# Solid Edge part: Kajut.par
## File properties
Author: Administrator
Template: Normal.par
Last saved by: Administrator
Revision: 10
Application: Solid Edge
Accuracy: 0,990
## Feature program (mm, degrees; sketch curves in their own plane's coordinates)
sketch for "unnamed Protrusion 1" plane through (0, 0, 0) normal (0, 0, 1) x-axis (1, 0, 0)
  line (-32.8942, 94.2848) -> (-32.8942, -94.2848)
extrude "unnamed Protrusion 1" add finite 2.5 along -normal
sketch for "ExtrudedProtrusion_2" plane through (0, 0, 0) normal (0, 0, 1) x-axis (1, 0, 0)
  line (319.6058, 0.75) -> (319.6058, -0.75)
  line (319.6058, -0.75) -> (317.1058, -0.75)
  line (317.1058, -0.75) -> (317.1058, 0.75)
  line (317.1058, 0.75) -> (319.6058, 0.75)
extrude "ExtrudedProtrusion_2" add finite 4.5 along -normal
lofted protrusion "unnamed LoftedProtrusion 1"
chamfer "Chamfer_1" setback 2.5
fillet "Round_3" radius 2.5
fillet "Round_4" radius 10
thinwall "Thinwall_1"  Thickness = 2.5 mm
sketch for "unnamed Cutout 1" plane through (52.968, -57.4403, 34.5811) normal (0.166663, -0.966314, 0.196116) x-axis (0.98545, 0.169964, 0)
  line (-46.8726, 23.0213) -> (63.1274, 23.0213)
  arc centre (63.1274, 15.5213) radius 7.5 from (63.1274, 23.0213) to (70.6274, 15.5213) cw
  line (70.6274, 15.5213) -> (70.6274, 10.5213)
  arc centre (63.1274, 10.5213) radius 7.5 from (63.1274, 3.0213) to (70.6274, 10.5213) ccw
  line (-46.8726, 3.0213) -> (63.1274, 3.0213)
  arc centre (-46.8726, 10.5213) radius 7.5 from (-54.3726, 10.5213) to (-46.8726, 3.0213) ccw
  line (-54.3726, 15.5213) -> (-54.3726, 10.5213)
  arc centre (-46.8726, 15.5213) radius 7.5 from (-54.3726, 15.5213) to (-46.8726, 23.0213) cw
extrude "unnamed Cutout 1" cut through along -normal
mirror "unnamed Mirror 1" of "unnamed Cutout 1" about plane through (0, 0, 0) normal (0, -1, 0)
extrude "unnamed Cutout 2" cut through
sketch for "unnamed Cutout 3" plane through (-32.8942, 0, 31.25) normal (-1, 0, 0) x-axis (0, -1, 0)
  line (-25, -33.75) -> (-25, 31.25)
  line (-25, 31.25) -> (25, 31.25)
  line (25, 31.25) -> (25, -33.75)
  line (25, -33.75) -> (-25, -33.75)
extrude "unnamed Cutout 3" cut through along -normal
fillet "Round_5" radius 2.45
sketch used by "ExtrudedCutout_4" plane through (78.9279, 0, 75) normal (0, 0, 1) x-axis (0, 1, 0)
extrude "ExtrudedCutout_4" cut finite 2 along -normal
fillet "Round_6" radius 0.5
sketch used by "unnamed Cutout 4" plane through (78.9279, 0, 75) normal (0, 0, 1) x-axis (0, 1, 0)
extrude "unnamed Cutout 4" cut through along -normal
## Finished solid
Body 1: solid body, 77 faces, 206 edges, 132 vertices.
  Faces by surface: plane 35, cylinder 20, blend 12, offset 4, spline 4, swept 2
  Edges by curve: line 110, intersection 44, circle 25, ellipse 16, curve on surface 9, spline 2
Bounding box of the edges (mm; curved faces can reach further): 357.500 x 188.570 x 79.500, from (-32.8942, -94.2848, -4.5) to (324.6058, 94.2848, 75).
Cylindrical faces by radius (mm): R0.5 x1, R2.45 x2, R2.5 x2, R7.5 x11, R10 x3, R20 x1
Planar faces by outward normal: +x 3, +y 3, +z 3, -x 3, -y 3, -z 4, oblique 16
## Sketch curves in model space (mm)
line (-32.8942, -25, 62.5) -> (-32.8942, -25, -2.5)
line (-32.8942, -25, -2.5) -> (-32.8942, 25, -2.5)
line (-32.8942, 25, -2.5) -> (-32.8942, 25, 62.5)
line (-32.8942, 25, 62.5) -> (-32.8942, -25, 62.5)
arc centre (114.6596, -43.7112, 49.801) radius 7.5 from (114.4096, -42.2617, 57.1554) through (119.8639, -41.7893, 54.8479) to (122.0504, -42.4365, 49.801)
line (122.0504, -42.4365, 49.801) -> (122.2171, -43.4028, 44.8981)
arc centre (114.8262, -44.6775, 44.8981) radius 7.5 from (115.0762, -46.127, 37.5437) through (120.3737, -44.745, 39.8512) to (122.2171, -43.4028, 44.8981)
line (6.6767, -64.823, 37.5437) -> (115.0762, -46.127, 37.5437)
arc centre (6.4267, -63.3735, 44.8981) radius 7.5 from (-0.9642, -64.6482, 44.8981) through (1.5366, -65.3026, 39.5487) to (6.6767, -64.823, 37.5437)
line (-1.1309, -63.6819, 49.801) -> (-0.9642, -64.6482, 44.8981)
arc centre (6.26, -62.4072, 49.801) radius 7.5 from (-1.1309, -63.6819, 49.801) through (1.0062, -62.2277, 55.1504) to (6.01, -60.9577, 57.1554)
line (6.01, -60.9577, 57.1554) -> (114.4096, -42.2617, 57.1554)
circle centre (32.1058, 0, 75) radius 20
line (32.1058, -8.7172, 75) -> (32.1058, 27.1978, 75)
line (-20.3942, 37.5, 75) -> (-19.3942, 37.5, 75)
line (-19.3942, 37.5, 75) -> (-19.3942, -37.5, 75)
line (-19.3942, -37.5, 75) -> (-20.3942, -37.5, 75)
line (-20.3942, -37.5, 75) -> (-20.3942, 37.5, 75)
line (130.9234, 35.7919, 75) -> (192.9706, 0, 75)
line (130.9234, -35.7919, 75) -> (192.9706, 0, 75)
line (-32.8942, -64.046, 75) -> (130.9234, -35.7919, 75)
line (-32.8942, 64.046, 75) -> (-32.8942, -64.046, 75)
line (-32.8942, 64.046, 75) -> (130.9234, 35.7919, 75)
line (134.6324, 50.3737, 0) -> (282.9706, 0, 0)
line (134.6324, -50.3737, 0) -> (282.9706, 0, 0)
line (-32.8941, -79.2675, 0) -> (134.6324, -50.3737, 0)
line (-32.8941, 79.2675, 0) -> (-32.8941, -79.2675, 0)
line (-32.8941, 79.2675, 0) -> (134.6324, 50.3737, 0)
line (317.1058, 4.7553, 0) -> (317.1058, 48.9209, 0)
spline (324.6058, 0, 0) -> (262.2322, 23.8432, 0) -> (-32.8942, 94.2848, 0)
line (-32.8942, 94.2848, 0) -> (-32.8942, -94.2848, 0)
spline (-32.8942, -94.2848, 0) -> (265.0138, -22.8081, 0) -> (324.6058, 0, 0)
line (319.6058, 0.75, 0) -> (319.6058, -0.75, 0)
line (319.6058, -0.75, 0) -> (317.1058, -0.75, 0)
line (317.1058, -0.75, 0) -> (317.1058, 0.75, 0)
line (317.1058, 0.75, 0) -> (319.6058, 0.75, 0)
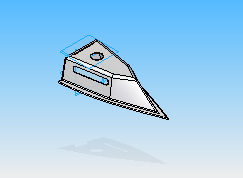
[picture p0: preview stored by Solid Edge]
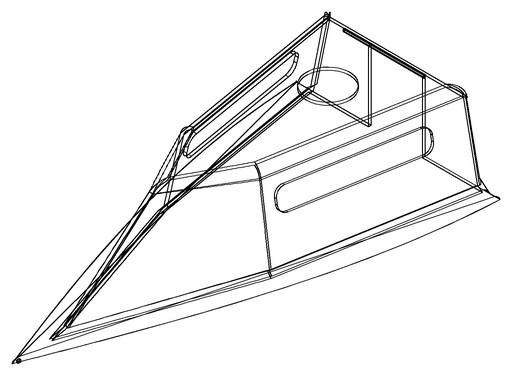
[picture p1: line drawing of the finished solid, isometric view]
